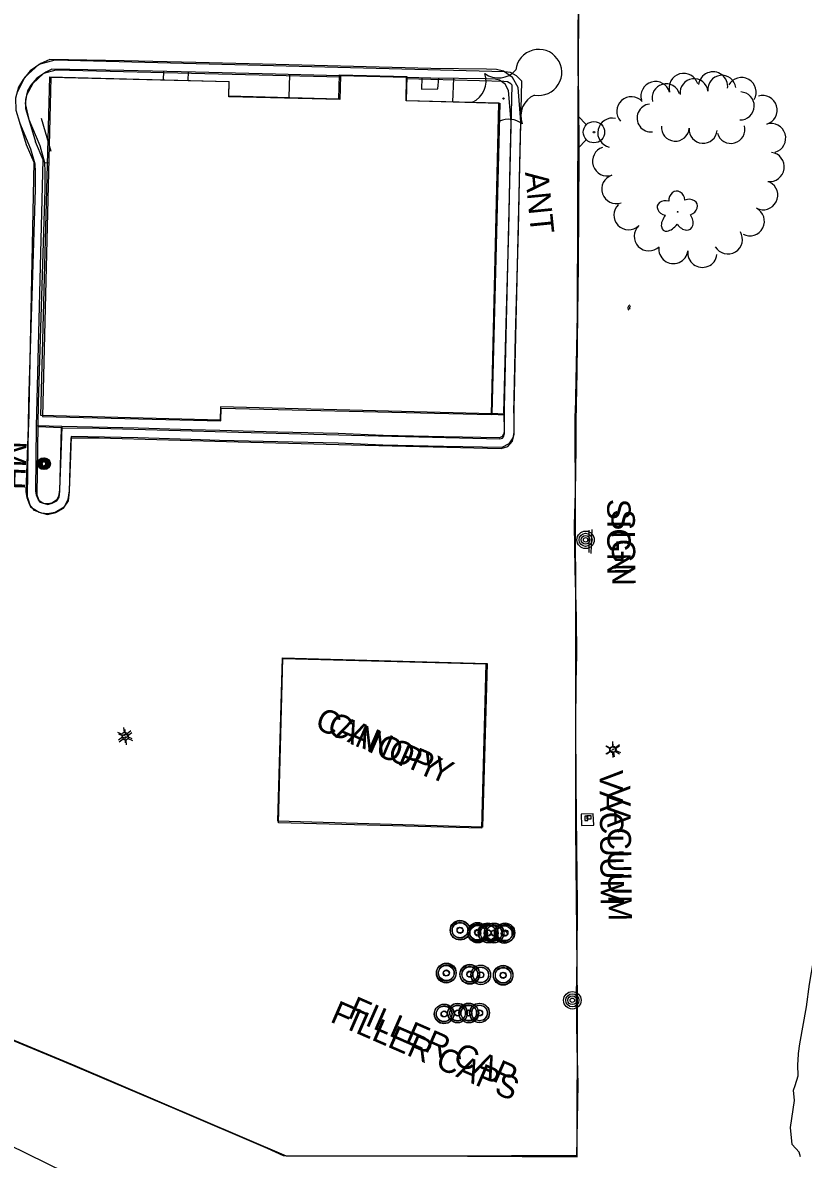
# Model space of a CAD drawing. Extents: x 588843 to 2552415, y 180129 to 269402.
# Drawn here: x 593615.7 to 593816, y 185762.9 to 186054.6 of the extents above; entities that cross this region are included whole.
import ezdxf

# ---------------------------------------------------------------- set-up
doc = ezdxf.new("R2010")
doc.units = 0
for name, color, linetype in [('Default', 7, 'Continuous'), ('E_AREA', 7, 'Continuous'), ('E_BLD', 7, 'Continuous'), ('E_BLD_HvyDash', 7, 'Continuous'), ('E_BLD_Text', 7, 'Continuous'), ('E_BLD_Vacuum', 7, 'Continuous'), ('E_DRN', 7, 'Continuous'), ('E_DWY', 7, 'Continuous'), ('E_LAND_TreeLine_P', 7, 'Continuous'), ('E_LAND_Vegetation', 7, 'Continuous'), ('E_LTG', 7, 'Continuous'), ('E_MISCPROP', 7, 'Continuous'), ('E_MISCPROP_Text', 7, 'Continuous'), ('E_PATH_Sidewalk', 7, 'Continuous'), ('E_SGN', 7, 'Continuous'), ('E_SGN_Text', 7, 'Continuous'), ('E_UTL_MH', 7, 'Continuous'), ('E_UTL_MH_Text', 7, 'Continuous'), ('E_UTL_WHydrant', 7, 'Continuous'), ('E_WTR_P', 7, 'Continuous')]:
    doc.layers.add(name, color=color, linetype=linetype)

# ---------------------------------------------------------------- blocks, each defined once
blk = doc.blocks.new('LPOL')
at = {"layer": 'Default'}
for p, q in [((-4, 0), (-1.5, 0)), ((-0.75, 1.3), (-2, 3.46)), ((0.75, 1.3), (2, 3.46)), ((1.5, 0), (4, 0)), ((-2, -3.46), (-0.75, -1.3)), ((2, -3.46), (0.75, -1.3))]:
    blk.add_line(p, q, dxfattribs=at)
for radius in [1.5, 1.5, 1.5, 0.125]:
    blk.add_circle((0, 0), radius, dxfattribs=at)
blk = doc.blocks.new('POLE')
at = {"layer": 'Default'}
for radius in [4.46, 3.35, 2.23, 1.12]:
    blk.add_circle((0, 0), radius, dxfattribs=at)
blk = doc.blocks.new('FILO')
at = {"layer": 'E_MISCPROP'}
for radius in [5, 4, 1.5]:
    blk.add_circle((0, 0), radius, dxfattribs=at)
blk = doc.blocks.new('FILT')
at = {"layer": 'E_MISCPROP_Text'}
blk.add_text('FILLER CAPS', height=12, dxfattribs=at).set_placement((12, -4))
blk = doc.blocks.new('CANOPY')
at = {"layer": 'E_BLD_Text'}
blk.add_text('CANOPY', height=12, dxfattribs=at).set_placement((-32.52, -6))
blk = doc.blocks.new('MHO')
at = {"layer": 'Default'}
for centre, radius in [((0.08, -0.12), 3), ((0.08, -0.12), 2.43), ((0.07, -0.15), 1.94), ((0.02, -0.16), 1.21)]:
    blk.add_circle(centre, radius, dxfattribs=at)
blk = doc.blocks.new('VACO')
at = {"layer": 'E_BLD_Vacuum'}
blk.add_lwpolyline([(0, 1.5), (0, 0), (2.2, 0), (2.2, 1.5), (0, 1.5)], close=True, dxfattribs=at)
blk = doc.blocks.new('VAC')
at = {"layer": 'E_BLD_Text'}
blk.add_text('VACUUM', height=12, dxfattribs=at).set_placement((-33.33, -6))
blk = doc.blocks.new('SIGN')
at = {"layer": 'Default'}
blk.add_text('SIGN', height=12, dxfattribs=at).set_placement((-18.55, -6))
blk = doc.blocks.new('DTRE')
at = {"layer": 'Default'}
blk.add_circle((-0.18, 0), 0.183, dxfattribs=at)
for centre, major_axis, ratio in [((-1.87, 5.32), (1.36, -4.98), 0.782863), ((4.06, 2.74), (-5.27, -2.93), 0.691916), ((-5.87, 0.15), (4.93, -0.12), 0.832022), ((-2.49, -5.24), (1.8, 4.86), 0.716896), ((3.54, -3.71), (-5.01, 4.58), 0.560249)]:
    blk.add_ellipse(centre, major_axis=major_axis, ratio=ratio, start_param=1.570796, end_param=4.712389, dxfattribs=at)
blk = doc.blocks.new('CULV2')
at = {"layer": 'E_DRN'}
blk.add_arc((20, 15), 24.6, 216.8699, 323.1301, dxfattribs=at)
blk = doc.blocks.new('HYD')
at = {"layer": 'Default'}
for p, q in [((-3.84, 3.84), (-8.32, 8.32)), ((3.84, 3.84), (8.32, 8.32))]:
    blk.add_line(p, q, dxfattribs=at)
for radius in [5.48, 0.42]:
    blk.add_circle((0, 0), radius, dxfattribs=at)
blk = doc.blocks.new('U277')
at = {"layer": 'E_LAND_Vegetation'}
blk.add_circle((-0.01, 0.01), 0.167, dxfattribs=at)
for centre, radius, start, end in [((9.05, 6.74), 5.91, 259.4341, 173.758), ((-10.36, 4.49), 5.9, 293.7182, 19.4831), ((-1.31, 11.21), 5.9, 233.7182, 319.4831), ((10.33, -4.47), 5.9, 113.7182, 199.4831), ((-9.01, -6.69), 5.9, 75.8399, 79.4785), ((1.28, -11.19), 5.9, 53.7182, 112.948)]:
    blk.add_arc(centre, radius, start, end, dxfattribs=at)
blk = doc.blocks.new('FILO_1')
at = {"layer": 'E_MISCPROP'}
for radius in [16.4, 13.1, 4.92]:
    blk.add_circle((0, 0), radius, dxfattribs=at)
blk = doc.blocks.new('FILT_6')
at = {"layer": 'E_MISCPROP_Text'}
blk.add_text('FILLER CAP', height=39.37, dxfattribs=at).set_placement((32.8, -19.7))
blk = doc.blocks.new('CULV2_4')
at = {"layer": 'E_DRN'}
blk.add_arc((65, 48), 80.7, 216.8699, 323.1301, dxfattribs=at)
blk = doc.blocks.new('MHO_3')
at = {"layer": 'E_UTL_MH'}
for centre, radius in [((0.3, -0.4), 9.84), ((0.3, -0.4), 7.98), ((0.2, -0.5), 6.35), ((0.1, -0.5), 3.97)]:
    blk.add_circle(centre, radius, dxfattribs=at)
blk = doc.blocks.new('MHT_3')
at = {"layer": 'E_UTL_MH_Text'}
blk.add_text('MH', height=39.37, dxfattribs=at).set_placement((-32.2, -19.7))
blk = doc.blocks.new('VACO_1')
at = {"layer": 'E_BLD_Vacuum'}
blk.add_lwpolyline([(0, 4.9), (0, 0), (7.2, 0), (7.2, 4.9)], close=True, dxfattribs=at)
blk = doc.blocks.new('VAC_1')
at = {"layer": 'E_BLD_Text'}
blk.add_text('VACUUM', height=39.37, dxfattribs=at).set_placement((-109.3, -19.7))
blk = doc.blocks.new('ANT_1_1')
at = {"layer": 'E_MISCPROP_Text'}
blk.add_text('ANT', height=39.37, dxfattribs=at).set_placement((-50.5, -19.7))
blk = doc.blocks.new('LPOL_4')
at = {"layer": 'E_LTG'}
for p, q in [((-13.1, 0), (-4.9, 0)), ((-2.5, 4.3), (-6.6, 11.4)), ((2.5, 4.3), (6.6, 11.4)), ((4.9, 0), (13.1, 0)), ((-6.6, -11.4), (-2.5, -4.3)), ((6.6, -11.4), (2.5, -4.3))]:
    blk.add_line(p, q, dxfattribs=at)
for radius in [4.92, 4.92, 4.92, 0.41]:
    blk.add_circle((0, 0), radius, dxfattribs=at)
blk = doc.blocks.new('SIGN_3')
at = {"layer": 'E_SGN'}
blk.add_text('SIGN', height=39.37, dxfattribs=at).set_placement((-56.1, -19.7))
blk = doc.blocks.new('CANOPY_1')
at = {"layer": 'E_BLD_Text'}
blk.add_text('CANOPY', height=39.37, dxfattribs=at).set_placement((-106.7, -19.7))

msp = doc.modelspace()

# ---------------------------------------------------------------- linework, layer by layer
at = {"layer": 'E_AREA'}
msp.add_lwpolyline([(593759.13, 185848.56), (593762.29, 185848.68), (593762.17, 185851.6), (593759.02, 185851.48)], close=True, dxfattribs=at)
at = {"layer": 'E_BLD'}
for points in [[(593736.12, 185954.19), (593666.51, 185956.02), (593666.42, 185952.62), (593620.42, 185953.83), (593622.7, 186040.7), (593668.64, 186039.49), (593668.54, 186035.8), (593696.84, 186035.06), (593697, 186041.25), (593714.31, 186040.8), (593714.14, 186034.6), (593738.22, 186033.97), (593736.12, 185954.19)], [(593736.01, 185954.03), (593737.95, 186033.97), (593714.12, 186034.54), (593714.26, 186040.54), (593697.25, 186040.95), (593697.11, 186034.87), (593668.64, 186035.56), (593668.73, 186039.4), (593622.96, 186040.51), (593620.85, 185953.5), (593666.59, 185952.39), (593666.67, 185955.71)]]:
    msp.add_lwpolyline(points, close=True, dxfattribs=at)
at = {"layer": 'E_BLD_HvyDash'}
for points in [[(593682.38, 185891.6), (593734.91, 185890.11), (593733.71, 185848.19), (593681.19, 185849.69), (593682.38, 185891.6)], [(593682.51, 185891.43), (593734.59, 185890.03), (593733.46, 185847.89), (593681.38, 185849.29)]]:
    msp.add_lwpolyline(points, close=True, dxfattribs=at)
at = {"layer": 'E_DWY'}
for points in [[(593758.5, 186081.05), (593758.2, 186032.26), (593758.01, 185979.59), (593757.53, 185954.3)], [(593758.32, 186061.09), (593758.23, 186049.82), (593758.23, 186042.56), (593758.35, 186035.73), (593758.43, 186020.91), (593758.35, 186006.67), (593758.26, 185992.42), (593758.1, 185979.92), (593757.96, 185964.93), (593757.7, 185952.37), (593757.71, 185945.57), (593757.52, 185933.96), (593757.27, 185925.85), (593757.41, 185914.35), (593757.75, 185901.87), (593757.87, 185892.43), (593757.69, 185885.27), (593757.56, 185874.31), (593757.66, 185859.55), (593757.85, 185843.12), (593758.05, 185828.29), (593757.95, 185814.85), (593757.75, 185804.75), (593757.9, 185791.9), (593758.22, 185782.16), (593757.86, 185763.84), (593741.17, 185763.76), (593719.5, 185763.69), (593701, 185763.73), (593689, 185763.74), (593685.97, 185763.71), (593682.69, 185763.84), (593678.56, 185765.64), (593655.36, 185775.64), (593626.39, 185787.96), (593604.22, 185797.06)], [(593741.73, 185954.41), (593742.21, 185974.22), (593742.96, 186001.42), (593743.33, 186018.43), (593743.56, 186029.13), (593742.9, 186037.98), (593741.44, 186040.54), (593739.16, 186042.14), (593737.35, 186042.61), (593734.78, 186042.66), (593720.49, 186042.89), (593697.3, 186043.44), (593680.68, 186043.92), (593660.13, 186044.43), (593641.74, 186044.83), (593622.72, 186045.15), (593620.4, 186044.13), (593617.68, 186042.21), (593615.83, 186040.04), (593614.67, 186038.08), (593613.91, 186035.2), (593614.01, 186032.18), (593614.88, 186029.08), (593616.64, 186023.32)], [(593635.31, 185948.05), (593671.02, 185947.05), (593700.08, 185946.25), (593738.5, 185945.3), (593740.23, 185945.8), (593741.42, 185947.18), (593741.85, 185948.92), (593741.84, 185955.71), (593742.47, 185981.42), (593743.84, 186039.59), (593742.47, 186040.96), (593740.95, 186041.79), (593739.43, 186042.03), (593623.97, 186044.96), (593619.84, 186043.84), (593616.31, 186040.59), (593614.3, 186036.82)], [(593697.25, 186040.6), (593624.27, 186042.45), (593621.08, 186041.58), (593618.31, 186039.04), (593616.71, 186036.03), (593616.41, 186033.85), (593617.34, 186029.76), (593620.11, 186023.07), (593621.36, 186018.76), (593621.44, 186016.34), (593621.44, 186011.77), (593619.72, 185957.12), (593619.37, 185933.43), (593619.84, 185932.03), (593620.97, 185931.32), (593622.17, 185930.97), (593623.3, 185931.26), (593624.47, 185931.93), (593625.11, 185932.83), (593625.28, 185934.42), (593625.46, 185940.7)], [(593696.99, 186040.94), (593680.61, 186041.42), (593660.07, 186041.93), (593641.7, 186042.33), (593623.22, 186042.65), (593621.64, 186041.95), (593619.38, 186040.35), (593617.87, 186038.58), (593617, 186037.11), (593616.43, 186034.92), (593616.5, 186032.56), (593617.28, 186029.79), (593619.03, 186024.05)], [(593635.38, 185950.55), (593671.09, 185949.55), (593700.15, 185948.74), (593738.18, 185947.81), (593738.82, 185948), (593739.14, 185948.36), (593739.35, 185949.22), (593739.34, 185955.73), (593739.97, 185981.48), (593741.31, 186038.58), (593740.96, 186038.94), (593740.13, 186039.39), (593739.2, 186039.54), (593714.25, 186040.17)], [(593739.23, 185954.47), (593739.71, 185974.29), (593740.46, 186001.48), (593740.83, 186018.49), (593741.05, 186029.06), (593740.44, 186037.23), (593739.54, 186038.82), (593738.09, 186039.84), (593737.01, 186040.11), (593734.73, 186040.16), (593720.44, 186040.39), (593714.3, 186040.53)], [(593614.95, 186029), (593617.75, 186022.24), (593618.87, 186018.36), (593618.94, 186016.3), (593618.94, 186011.81), (593617.22, 185957.18), (593616.86, 185933.04), (593617.75, 185930.39), (593619.93, 185929.02), (593622.13, 185928.38), (593624.26, 185928.93), (593626.18, 185930.03), (593627.52, 185931.91), (593627.78, 185934.24), (593627.96, 185940.63)], [(593616.64, 186023.32), (593618.6, 186018.82), (593617.23, 185950.83)], [(593619.3, 185951.03), (593620.99, 186019.44), (593619.03, 186024.05)], [(593561.3, 185898.37), (593561.59, 185836.43), (593592.09, 185836.3), (593585.32, 185824.31), (593579.2, 185807.78), (593629.08, 185786.97), (593683.34, 185763.77), (593715.78, 185763.83), (593758.03, 185763.57), (593758.13, 185803.19), (593757.72, 185847.98), (593757.71, 185903.71), (593757.53, 185954.3)], [(593741.73, 185954.41), (593741.76, 185949.45), (593741.53, 185948.09), (593740.5, 185946.53), (593738.72, 185945.58), (593723.73, 185945.83), (593708.12, 185946.2), (593696.65, 185946.69), (593681.17, 185947.03), (593666.27, 185947.41), (593658.9, 185947.63), (593645.28, 185948.04), (593628.17, 185948.41), (593627.99, 185943.51), (593627.7, 185934.5), (593627.35, 185932.23), (593626.35, 185930.27), (593624.11, 185928.9), (593622.13, 185928.6), (593620.58, 185928.76), (593618.8, 185929.39), (593617.59, 185930.88), (593616.85, 185932.64), (593616.59, 185934.28), (593617.23, 185950.83)], [(593739.23, 185954.47), (593739.27, 185949.69), (593739.15, 185949.03), (593738.76, 185948.43), (593738.12, 185948.09), (593723.78, 185948.33), (593708.2, 185948.7), (593696.73, 185949.19), (593681.23, 185949.53), (593666.34, 185949.91), (593658.97, 185950.13), (593645.35, 185950.54), (593625.77, 185950.96), (593625.49, 185943.59), (593625.21, 185934.73), (593624.94, 185933.01), (593624.44, 185932.03), (593623.24, 185931.3), (593622.07, 185931.12), (593621.13, 185931.21), (593620.3, 185931.51), (593619.76, 185932.18), (593619.27, 185933.33), (593619.09, 185934.45), (593619.3, 185951.03)], [(593625.46, 185940.7), (593625.73, 185950.61), (593635.38, 185950.55)], [(593627.96, 185940.63), (593628.16, 185948.09), (593635.37, 185948.05)]]:
    msp.add_lwpolyline(points, dxfattribs=at)
at = {"layer": 'E_LAND_TreeLine_P'}
for centre, radius, start, end in [((593778.13, 186035.75), 3.76, 16.1377, 196.1377), ((593785.35, 186037.84), 3.76, 16.1377, 196.1377), ((593788.03, 186036.63), 3.59, 7.1155, 187.1155), ((593792.9, 186038.24), 3.76, 352.914, 172.914), ((593795.15, 186037.52), 3.59, 7.1155, 187.1155), ((593800.18, 186036.78), 3.76, 330.3335, 150.3335), ((593780.84, 186035.33), 3.59, 15.8027, 195.8027), ((593799.86, 186033.24), 3.59, 268.041, 88.041), ((593771.93, 186031.83), 3.76, 42.2453, 222.2453), ((593776.97, 186030.15), 3.59, 96.2069, 276.2069), ((593805.61, 186032.18), 3.76, 286.7934, 106.7934), ((593767.06, 186026.37), 3.76, 77.4619, 257.4619), ((593783.2, 186027.8), 3.59, 175.4862, 355.4862), ((593790.35, 186027.24), 3.59, 175.4862, 355.4862), ((593797.46, 186027.21), 3.59, 195.3495, 15.3495), ((593807.78, 186024.99), 3.76, 286.7934, 106.7934), ((593765.71, 186019.05), 3.76, 108.4829, 288.4829), ((593807.41, 186017.59), 3.76, 262.4422, 82.4422), ((593768.1, 186011.92), 3.76, 108.4829, 288.4829), ((593805.74, 186010.35), 3.76, 242.8082, 62.8082), ((593771.2, 186005.23), 3.76, 133.9149, 313.9149), ((593802.3, 186003.66), 3.76, 242.8082, 62.8082), ((593776.42, 185999.81), 3.76, 133.9149, 313.9149), ((593796.68, 185999.01), 3.76, 211.2247, 31.2247), ((593782.71, 185996.53), 3.76, 172.5872, 352.5872), ((593790.16, 185995.56), 3.76, 172.5872, 352.5872)]:
    msp.add_arc(centre, radius, start, end, dxfattribs=at)
at = {"layer": 'E_PATH_Sidewalk'}
for points in [[(593651.86, 186042.11), (593651.82, 186039.93)], [(593658.18, 186041.97), (593658.12, 186039.77)], [(593684.23, 186041.31), (593684.02, 186035.4)], [(593718.2, 186040.44), (593718.05, 186037.59), (593722.31, 186037.61), (593722.51, 186040.36)], [(593726.25, 186040.3), (593726.06, 186034.29)], [(593621.36, 186018.75), (593622.43, 186018.63)], [(593739.34, 185953.86), (593736.01, 185954.07)], [(593739.23, 185954.1), (593736.13, 185954.3)], [(593625.77, 185950.96), (593619.3, 185951.15)], [(593625.73, 185950.61), (593619.63, 185950.91)]]:
    msp.add_lwpolyline(points, dxfattribs=at)
at = {"layer": 'E_SGN'}
for p, q in [((593620.48, 186030.13), (593622.94, 186021.64)), ((593761.75, 185924.53), (593761.5, 185918.39))]:
    msp.add_line(p, q, dxfattribs=at)
msp.add_lwpolyline([(593761.04, 185924.36), (593761.01, 185918.61)], dxfattribs=at)
at = {"layer": 'E_WTR_P'}
for points in [[(593814.81, 185790.08), (593815.13, 185792.57), (593816.85, 185802.04), (593817.64, 185807.85), (593819.26, 185817.38)], [(593815.31, 185763.53), (593815, 185764.71), (593813.15, 185766.74), (593812.73, 185771.06), (593813.75, 185777.98), (593813.56, 185780.64), (593813.97, 185781.85), (593814.75, 185784.34), (593814.62, 185787.19), (593814.78, 185789.8), (593814.81, 185790.07)], [(593609.19, 185767.74), (593612.06, 185766.71), (593631.41, 185757.17), (593635.93, 185754.95)]]:
    msp.add_lwpolyline(points, dxfattribs=at)

# ---------------------------------------------------------------- block references
at = {"layer": 'E_BLD_Text'}
for name, p, xscale, yscale, rotation in [('CANOPY', (593706.52, 185869.88), 0.49999999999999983, 0.49999999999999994, -23.52992746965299), ('CANOPY_1', (593709.59, 185868.76), 0.1524003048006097, 0.1524003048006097, -23.3958839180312), ('VAC', (593766.9, 185846.15), 0.4999999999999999, 0.49999999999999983, -89.47457921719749), ('VAC_1', (593768.88, 185842.14), 0.1524003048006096, 0.1524003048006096, -89.2544447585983)]:
    msp.add_blockref(name, p, dxfattribs=dict(at, xscale=xscale, yscale=yscale, rotation=rotation))
at = {"layer": 'E_BLD_Vacuum'}
for name, p, xscale, yscale, rotation in [('VACO', (593759.99, 185850.95), 0.4999999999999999, 0.49999999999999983, -89.47457921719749), ('VACO_1', (593761.64, 185851.05), 0.1524003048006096, 0.15240030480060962, 178.95888481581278)]:
    msp.add_blockref(name, p, dxfattribs=dict(at, xscale=xscale, yscale=yscale, rotation=rotation))
at = {"layer": 'E_DRN'}
for name, p, xscale, yscale, rotation in [('CULV2_4', (593771.5, 185982.12), 0.009916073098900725, 0.009916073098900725, -101.23159876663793), ('CULV2', (593771.67, 185981.87), 0.018930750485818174, 0.01893075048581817, -95.62321378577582)]:
    msp.add_blockref(name, p, dxfattribs=dict(at, xscale=xscale, yscale=yscale, rotation=rotation))
at = {"layer": 'E_LAND_Vegetation'}
msp.add_blockref('U277', (593739.12, 186035.11), dxfattribs=at)
at = {"layer": 'E_LAND_Vegetation', "xscale": 0.4999999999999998, "yscale": 0.4999999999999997, "rotation": -84.33700075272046}
msp.add_blockref('DTRE', (593783.82, 186005.99), dxfattribs=at)
at = {"layer": 'E_LTG'}
for name, p, xscale, yscale, rotation in [('LPOL', (593641.92, 185871.74), 0.49999999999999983, 0.49999999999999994, -23.52992746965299), ('LPOL_4', (593642.11, 185871.26), 0.1524003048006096, 0.15240030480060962, -84.36014555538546), ('LPOL_4', (593767.28, 185868.15), 0.1524003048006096, 0.15240030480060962, -84.36014555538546), ('LPOL', (593767.12, 185868), 0.5000000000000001, 0.5, -89.67337617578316)]:
    msp.add_blockref(name, p, dxfattribs=dict(at, xscale=xscale, yscale=yscale, rotation=rotation))
at = {"layer": 'E_MISCPROP'}
for name, p, xscale, yscale, rotation in [('POLE', (593760.19, 185921.89), 0.4999999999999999, 0.4999999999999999, -57.756605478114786), ('FILO', (593727.94, 185821.75), 0.4999999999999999, 0.4999999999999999, -57.756605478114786), ('FILO_1', (593727.99, 185821.64), 0.15240030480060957, 0.1524003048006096, -97.42674805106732), ('FILO', (593732.45, 185821.2), 0.4999999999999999, 0.4999999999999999, -57.756605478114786), ('FILO_1', (593732.52, 185820.93), 0.15240030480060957, 0.1524003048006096, -97.42674805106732), ('FILO', (593735.13, 185821.09), 0.4999999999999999, 0.4999999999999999, -57.756605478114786), ('FILO_1', (593735.25, 185820.93), 0.15240030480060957, 0.1524003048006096, -97.42674805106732), ('FILO', (593736.74, 185821.03), 0.4999999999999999, 0.4999999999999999, -57.756605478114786), ('FILO_1', (593736.67, 185820.92), 0.15240030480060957, 0.1524003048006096, -97.42674805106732), ('FILO', (593739.51, 185821.06), 0.4999999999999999, 0.4999999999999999, -57.756605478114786), ('FILO_1', (593739.29, 185820.83), 0.15240030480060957, 0.1524003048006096, -97.42674805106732), ('FILO', (593724.48, 185810.78), 0.4999999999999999, 0.4999999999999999, -57.756605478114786), ('FILO_1', (593724.41, 185810.65), 0.15240030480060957, 0.1524003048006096, -97.42674805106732), ('FILO', (593730.45, 185810.46), 0.4999999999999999, 0.4999999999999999, -57.756605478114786), ('FILO_1', (593730.48, 185810.33), 0.15240030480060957, 0.1524003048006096, -97.42674805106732), ('FILO', (593733.31, 185810.26), 0.4999999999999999, 0.4999999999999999, -57.756605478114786), ('FILO_1', (593733.27, 185810.22), 0.15240030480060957, 0.1524003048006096, -97.42674805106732), ('FILO', (593739.03, 185810.2), 0.4999999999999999, 0.4999999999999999, -57.756605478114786), ('FILO_1', (593739.02, 185810.08), 0.15240030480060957, 0.1524003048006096, -97.42674805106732), ('POLE', (593756.78, 185803.71), 0.4999999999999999, 0.4999999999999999, -57.756605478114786), ('FILO', (593723.92, 185800.26), 0.4999999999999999, 0.4999999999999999, -57.756605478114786), ('FILO_1', (593723.85, 185800.18), 0.15240030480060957, 0.1524003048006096, -97.42674805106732), ('FILO', (593727.36, 185800.48), 0.4999999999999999, 0.4999999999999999, -57.756605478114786), ('FILO_1', (593727.32, 185800.41), 0.15240030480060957, 0.1524003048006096, -97.42674805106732), ('FILO', (593730.17, 185800.51), 0.4999999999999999, 0.4999999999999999, -57.756605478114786), ('FILO_1', (593730.25, 185800.39), 0.15240030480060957, 0.1524003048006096, -97.42674805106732), ('FILO', (593732.94, 185800.48), 0.4999999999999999, 0.4999999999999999, -57.756605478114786), ('FILO_1', (593733.01, 185800.46), 0.15240030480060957, 0.1524003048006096, -97.42674805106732)]:
    msp.add_blockref(name, p, dxfattribs=dict(at, xscale=xscale, yscale=yscale, rotation=rotation))
at = {"layer": 'E_MISCPROP_Text'}
for name, p, xscale, yscale, rotation in [('ANT_1_1', (593748.37, 186008.84), 0.1524003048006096, 0.15240030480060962, -84.36014555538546), ('FILT', (593689.67, 185802.53), 0.49999999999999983, 0.49999999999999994, -23.52992746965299), ('FILT_6', (593695.48, 185804.16), 0.15240030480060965, 0.15240030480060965, -23.65617054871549)]:
    msp.add_blockref(name, p, dxfattribs=dict(at, xscale=xscale, yscale=yscale, rotation=rotation))
at = {"layer": 'E_SGN_Text'}
for name, p, xscale, yscale, rotation in [('SIGN', (593768.74, 185923.12), 0.49999999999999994, 0.49999999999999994, -89.93026381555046), ('SIGN_3', (593769.9, 185921.15), 0.15240030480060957, 0.15240030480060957, -89.35171826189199)]:
    msp.add_blockref(name, p, dxfattribs=dict(at, xscale=xscale, yscale=yscale, rotation=rotation))
at = {"layer": 'E_UTL_MH'}
for name, p, xscale, yscale, rotation in [('MHO', (593621.05, 185941.5), 0.49999999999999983, 0.49999999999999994, -23.52992746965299), ('MHO_3', (593621.27, 185941.37), 0.15240030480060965, 0.15240030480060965, 87.97121561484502)]:
    msp.add_blockref(name, p, dxfattribs=dict(at, xscale=xscale, yscale=yscale, rotation=rotation))
at = {"layer": 'E_UTL_MH_Text', "xscale": 0.1524003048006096, "yscale": 0.1524003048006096, "rotation": -92.028784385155}
msp.add_blockref('MHT_3', (593613.59, 185942.33), dxfattribs=at)
at = {"layer": 'E_UTL_WHydrant', "xscale": 0.49999999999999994, "yscale": 0.5, "rotation": 89.89282070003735}
msp.add_blockref('HYD', (593762.33, 186026.51), dxfattribs=at)

doc.saveas('drawing.dxf')
